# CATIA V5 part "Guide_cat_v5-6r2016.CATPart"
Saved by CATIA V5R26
Part number: Guide
Bounding box of the stored display mesh (mm): x -25 to 25, y -50 to 25, z -10 to 10
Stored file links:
  D:\_Deepak\CATIA\CATIA V5 2015 Parts Files\Tutorial Files\Tutorials\c16_catia_v5_6r2016_tut\Slide Curve\Guide_cat_v5-6r2012.CATPart
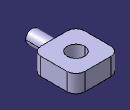
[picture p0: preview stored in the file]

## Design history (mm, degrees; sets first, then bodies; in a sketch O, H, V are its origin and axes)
Body1 (main body)
  Sketch1 on xy-plane, origin (0, 0, 0), H (1, 0, 0), V (0, 1, 0)
    circle A1 centre (0, 0) radius 10
    line L1 (-25, 25) -> (25, 25)
    line L2 (25, 25) -> (25, -25)
    line L3 (25, -25) -> (-25, -25)
    line L4 (-25, -25) -> (-25, 25)
    radius A1 = 10
    length L4 = 50
    length L3 = 50
    distance V L4 = 25
    distance L3 H = 25
    horizontal: L1 H, L3 H
    vertical: L2 V, L4 V
  Pad1: profile Sketch1, direction (0, 0, 1), length 10, mirrored extent
  Sketch2 on face of Pad1 from Sketch1.L3, origin (0, -25, 0), H (1, 0, 0), V (0, 0, 1)
    circle A1 centre (0, 0) radius 7.5
    point P1 (0, 0)
    reference projected line E1 (-25, 10) -> (25, 10) from edge [face of Pad1 from Sketch1.L3 | end face of Pad1]
    radius A1 = 7.5
    distance E1 P1 = 10
    coincidence: P1 V
  Pad2: profile Sketch2, direction (0, -1, 0), length 25
  Fillet1: radius 10, on edge [face of Pad1 from Sketch1.L2 | face of Pad1 from Sketch1.L3]; edge [face of Pad1 from Sketch1.L3 | face of Pad1 from Sketch1.L4]; edge [face of Pad1 from Sketch1.L1 | face of Pad1 from Sketch1.L2]; edge [face of Pad1 from Sketch1.L4 | face of Pad1 from Sketch1.L1]
  Fillet2: radius 2, on edge [face of Pad1 from Sketch1.L3 | face of Pad2 from Sketch2.A1]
